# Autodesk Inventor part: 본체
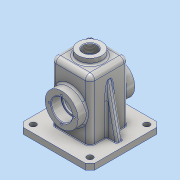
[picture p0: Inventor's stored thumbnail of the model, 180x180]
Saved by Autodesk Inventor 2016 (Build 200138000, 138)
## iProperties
Created: 2018-11
Part Number: 본체
Material: 알루미늄 6061
Document SubType Name: Modeling
Designer: user
Mass: 788.613 g
Surface Area: 899.375 cm^2
Volume: 292.079 cm^3
Density: 2.7 g/cm^3
Appearance: 알루미늄 - 평지
Author: user
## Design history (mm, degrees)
sketch "스케치1"
  geometry: L1 (-60, -60)-(60, -60); L2 (60, -60)-(60, 60); L3 (60, 60)-(-60, 60); L4 (-60, 60)-(-60, -60); L5 (-60, -60)-(60, 60); L6 (60, -60)-(-60, 60); 1 further point
  constraints: 12 end point, 2 midpoint, 2 parallel, 1 horizontal, 1 perpendicular
  dimensions: "d0" = 120 distance of L3.end L2.end; "d1" = 120 distance of L2.end L1.end
extrude "돌출1" new body sketch "스케치1" distance "d2" = 10; taper "d3" = 0 deg
sketch "스케치2"
  geometry: L1 (-32.5, 32.5)-(32.5, 32.5); L2 (32.5, 32.5)-(32.5, -32.5); L3 (32.5, -32.5)-(-32.5, -32.5); L4 (-32.5, -32.5)-(-32.5, 32.5); L5 (-32.5, 32.5)-(32.5, -32.5); L6 (32.5, 32.5)-(-32.5, -32.5); 1 further point
  constraints: 12 end point, 2 midpoint, 2 parallel, 1 horizontal, 1 perpendicular
  dimensions: "d4" = 65 distance of L2.end L3.end; "d5" = 65 distance of L1.end L2.end
extrude "돌출2" join sketch "스케치2" distance "d6" = 100; taper "d7" = 0 deg
sketch "스케치3"
  geometry: L1 (-27.5, -10)-(92.5, -10) reference; C1 r 27.5 at (32.5, 45); 2 further points
  constraints: 1 centre point, 1 midpoint, 1 vertical alignment
  dimensions: "d8" = 55 diameter of C1; "d9" = 55 distance from line of L1 C1.centre
extrude "돌출3" join sketch "스케치3" distance "d10" = 15; taper "d11" = 0 deg
sketch "스케치4"
  geometry: L1 (27.5, -27.5)-(-27.5, -27.5); L2 (-27.5, -27.5)-(-27.5, 27.5); L3 (-27.5, 27.5)-(27.5, 27.5); L4 (27.5, 27.5)-(27.5, -27.5); L5 (27.5, -27.5)-(-27.5, 27.5); L6 (-27.5, -27.5)-(27.5, 27.5); 4 further points
  constraints: 12 end point, 4 midpoint, 2 coincident, 2 parallel, 1 horizontal, 1 perpendicular
  dimensions: "d12" = 55 distance of L2.end L3.end; "d13" = 55 distance of L1.end L2.end
extrude "돌출4" cut sketch "스케치4" distance "d14" = 105; taper "d15" = 0 deg
sketch "스케치5"
  geometry: L1 (-60, -55)-(60, -55) reference; C1 r 17.5 at (0, 0); 2 further points
  constraints: 1 centre point, 1 midpoint, 1 vertical alignment
  dimensions: "d16" = 35 diameter of C1; "d17" = 55 distance from line of L1 C1.centre
extrude "돌출5" cut sketch "스케치5" distance "d18" = 17; taper "d19" = 0 deg
sketch "스케치6"
  geometry: L1 (-60, -55)-(60, -55) reference; C1 r 15 at (0, 0); 2 further points
  constraints: 1 centre point, 1 midpoint, 1 vertical alignment
  dimensions: "d20" = 30 diameter of C1; "d21" = 55 distance from line of L1 C1.centre
extrude "돌출6" cut sketch "스케치6" distance "d22" = 3; taper "d23" = 0 deg
sketch "스케치7"
  geometry: C1 r 20 at (0, 0); 1 further point
  constraints: 1 centre point, 1 coincident
  dimensions: "d24" = 40 diameter of C1
extrude "돌출7" join sketch "스케치7" distance "d25" = 10; taper "d26" = 0 deg
sketch "스케치8"
  geometry: 2 further points
  constraints: 1 coincident
hole "구멍1" sketch "스케치8" at (0, 0) diameter "d27" = 22.835; stored, may be unused: countersink angle "d31" = 90 deg, drill point angle "d33" = 118 deg; dims "d28" = 50, "d29" = 4, "d30" = 2, "d32" = 59.3
fillet "모깎기1" dims "d34" = 8
sketch "스케치9"
  geometry: L1 (-32.5, 92.331)-(-50, 10); L2 (-60, 0)-(-60, 10) reference; L3 (60, 10)-(-60, 10) reference; L4 (-32.5, 10)-(-32.5, 102) reference; 1 further point
  constraints: 2 end point, 2 point on line
  dimensions: "d35" = 10 distance from line of L2 L1.end; "d36" = 12 deg angle of L2 L1
feature "리브1" sketch "스케치9" dims "d37" = 1, "d38" = 10, "d39" = 0, "d40" = 0, "d41" = 1, "d42" = 1
chamfer "모따기1" distance "d43" = 8; stored, may be unused: second distance "d44" = 2, angle "d45" = 45 deg
sketch "스케치10"
  geometry: L1 (52, 55)-(-52, 55) reference; 3 further points
  constraints: 1 midpoint, 1 vertical alignment
  dimensions: "d46" = 76 distance from line of L1 point (0, -21)
hole "구멍2" sketch "스케치10" at (0, -21) diameter "d47" = 3.242; stored, may be unused: countersink angle "d51" = 90 deg, drill point angle "d53" = 118 deg; dims "d48" = 8, "d49" = 4, "d50" = 2, "d52" = 10
sketch "스케치11"
  geometry: L1 (-52, -60)-(52, -60) reference; C1 r 5 at (-47.5, -47.5); 1 further point
  constraints: 1 centre point
  dimensions: "d57" = 10 diameter of C1; "d59" = 47.5 horizontal distance of point (0, 0) C1.centre; "d60" = 47.5 horizontal distance of point (0, 0) C1.centre
extrude "돌출8" cut sketch "스케치11" distance "d61" = 100; taper "d62" = 0 deg
fillet "모깎기2" dims "d63" = 3
fillet "모깎기3" dims "d64" = 3
fillet "모깎기4" dims "d65" = 1
fillet "모깎기5" dims "d66" = 3
chamfer "모따기2" distance "d67" = 1; stored, may be unused: second distance "d68" = 2, angle "d69" = 45 deg
fillet "모깎기6" dims "d70" = 0.3
sketch "스케치12"
  geometry: L1 (57, 0)-(57, 91) reference; L2 (4.5, -18)-(44.5, -18) reference; 2 further points
  constraints: 1 other
  dimensions: "d71" = 32.5 distance from line of L1 point (24.5, 8); "d72" = 26 distance from line of L2 point (24.5, 8)
feature "엠보싱1" sketch "스케치12" dims "d0" = 120, "d1" = 120, "d73" = 0.5, "d74" = 0
node "솔리드1"
mirror "대칭1"
mirror "대칭2"
mirror "대칭3"
pattern_circular "원형 패턴1" dims angle "d55" = 360 deg
mirror "대칭4"
mirror "대칭5"
mirror "대칭6"
